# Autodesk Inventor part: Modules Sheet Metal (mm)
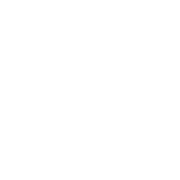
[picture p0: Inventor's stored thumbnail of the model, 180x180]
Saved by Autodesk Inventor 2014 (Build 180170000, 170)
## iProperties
Created: 2013-05
Part Number: Modules Sheet Metal (mm)
Material: Generic
Document SubType Name: Sheet Metal
Designer: Wally
Density: 1 g/cm^3
Sheet Metal Rule: Default
Appearance: Default
Author: Wally
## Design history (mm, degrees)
node "Sketch1"
other parameters: "Thickness" = 0.5, "BendRadius" = 0.5 (= Thickness), "BendReliefWidth" = 0.5 (= Thickness), "BendReliefDepth" = 0.25 (= 0.5 x Thickness), "CornerReliefSize" = 2 (= 4 x Thickness), "SeamGap" = 0.01, "MinimumRemnant" = 1 (= 2 x Thickness), "TransitionRadius" = 0.5 (= BendRadius), "JacobiRadiusSize" = 0.5 (= BendRadius), "GapSize" = 0.5 (= Thickness)
